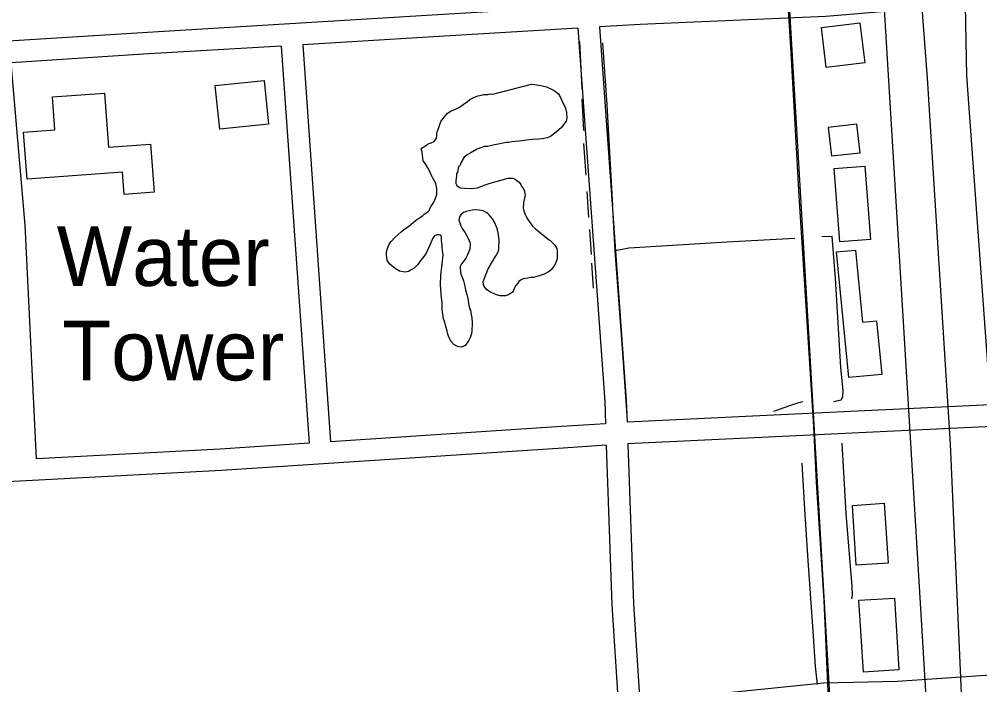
# Model space of a CAD drawing. Extents: x 3313447 to 3351316, y 703786 to 729172.
# Drawn here: x 3318120 to 3319454, y 712099 to 713023 of the extents above; entities that cross this region are included whole.
import ezdxf

# ---------------------------------------------------------------- set-up
doc = ezdxf.new("R2010")
doc.units = 0
for name, color, linetype in [('V-BLDG-OTLN', 7, 'Continuous'), ('V-DOMW-IDEN', 7, 'Continuous'), ('V-RAIL-TRAK', 7, 'Continuous'), ('V-ROAD-CNTR', 7, 'Continuous'), ('V-SITE-VEGE', 7, 'Continuous'), ('V-TOPO-SHOR', 7, 'Continuous')]:
    doc.layers.add(name, color=color, linetype=linetype)

msp = doc.modelspace()

# ---------------------------------------------------------------- linework, layer by layer
at = {"layer": 'V-BLDG-OTLN'}
for points in [[(3319294.4, 712962.4), (3319241, 712955.9), (3319234.3, 713011.4), (3319287.6, 713017.9)], [(3318466.4, 712877.4), (3318398.6, 712870.2), (3318392.2, 712930.9), (3318460, 712938.1)], [(3318238.2, 712920.5), (3318243.8, 712845.3), (3318302.2, 712849.7), (3318307.2, 712782.7), (3318265.5, 712779.6), (3318263.2, 712810.8), (3318130.8, 712800.9), (3318125.9, 712866), (3318169.4, 712869.3), (3318166, 712915.2)], [(3319243.7, 712872.8), (3319248.1, 712833.1), (3319287.9, 712837.5), (3319283.4, 712877.3)], [(3319259.7, 712713.7), (3319251.8, 712815.9), (3319294.4, 712819.2), (3319302.3, 712717)], [(3319272.3, 712525.4), (3319255, 712699.8), (3319281.4, 712702.4), (3319291.3, 712602.3), (3319310.7, 712604.2), (3319318, 712529.9)], [(3319282.5, 712264.7), (3319277.2, 712348), (3319321.6, 712350.8), (3319326.8, 712267.5)], [(3319292.5, 712116.5), (3319286.3, 712216.1), (3319335.7, 712219.1), (3319341.8, 712119.5)]]:
    msp.add_lwpolyline(points, close=True, dxfattribs=at)
at = {"layer": 'V-RAIL-TRAK'}
msp.add_lwpolyline([(3319315.7, 710879.4), (3319300.1, 711156.1), (3319292.5, 711279.1), (3319285.9, 711372.1), (3319282.6, 711439.6), (3319268.7, 711653.2), (3319259.6, 711840.3), (3319247.4, 712032.7), (3319244, 712078.9), (3319238.2, 712215.7), (3319227.6, 712380.3), (3319223.6, 712457.3), (3319217.1, 712559.1), (3319203.4, 712778), (3319192.1, 712976.4), (3319188.4, 713035.8), (3319181.3, 713174.6), (3319176.1, 713259.2)], dxfattribs=at)
at = {"layer": 'V-ROAD-CNTR'}
for points in [[(3319200.9, 715645.2), (3319216.7, 715284.7), (3319244.5, 714946.5), (3319270.4, 714529.8), (3319298.1, 714304.8), (3319315.2, 714045.1), (3319323.1, 713889.3), (3319368.3, 713112.6), (3319381.2, 712941.1), (3319413.2, 712432.8), (3319431.1, 712024.6), (3319452.3, 711724), (3319471.1, 711433.8), (3319475.9, 711305), (3319509.5, 710784.1), (3319530, 710456), (3319546.3, 710208.9), (3319558.3, 710026.2), (3319565.2, 709880.1), (3319575.7, 709725.1), (3319582.8, 709519.2), (3319592.9, 709284.4), (3319593.2, 709171.8)], [(3319104.4, 715556.2), (3319111.5, 715008.4), (3319106.8, 714793.8), (3319105.8, 714648.8), (3319107, 714540.6), (3319110.5, 714455.5), (3319112.5, 714365.8), (3319118.8, 714268.3), (3319122.2, 714163), (3319142.5, 713833.7), (3319173.1, 713319.1), (3319221.1, 712508.6), (3319264.3, 711756.9), (3319290.9, 711312.7), (3319362, 710097.5), (3319402.6, 709403.5), (3319416.2, 709171.5)], [(3319345.1, 714514.6), (3319371.4, 714068), (3319378, 713881.8), (3319405.6, 713508.6), (3319432.4, 713115.5), (3319435.8, 712944.4), (3319467.3, 712512), (3319484.1, 712134.4), (3319486.5, 712036.3), (3319512.8, 711766.8), (3319527.8, 711448.5), (3319527.4, 711327.4), (3319550.9, 711036.9), (3319567.8, 710785.7), (3319575.8, 710627.4), (3319594.4, 710397.1), (3319599, 710295), (3319616.4, 710052.6), (3319624.9, 709858.9), (3319631.7, 709695.3), (3319643.5, 709583.2), (3319653.2, 709388.3), (3319647.9, 709299.2), (3319653.3, 709171.9)], [(3319262.7, 713989.1), (3319296.4, 713448.2), (3319348.8, 712587.6), (3319394.3, 711836.6), (3319442.6, 710977.5), (3319493.5, 710218.9), (3319507.2, 709986.1)], [(3319720.9, 713095.9), (3319670, 713093.2), (3319238.6, 713056.7), (3318980.9, 713045.9), (3318693.7, 713028.5), (3318290.7, 713004.2), (3318030.2, 712987.7)], [(3319722.8, 713066), (3319672.1, 713063.3), (3319240.5, 713026.8), (3318982.4, 713015.9), (3318925.8, 713012.5)], [(3318895.9, 713010.7), (3318695.5, 712998.6), (3318514, 712987.6)], [(3318895.9, 713010.7), (3318933.2, 712492.1), (3318934.3, 712461.4)], [(3318925.8, 713012.5), (3318963.2, 712493.7), (3318964.2, 712463.5)], [(3318484, 712985.8), (3318292.5, 712974.3), (3318108.7, 712962.6)], [(3318484, 712985.8), (3318522.6, 712434.3)], [(3318514, 712987.6), (3318552.5, 712436.2)], [(3318143.9, 712412.7), (3318128.3, 712737.2), (3318108.7, 712962.6)], [(3319517.6, 712489.9), (3318964.2, 712463.5)], [(3318934.3, 712461.4), (3318873.4, 712457.3), (3318552.5, 712436.2)], [(3319520.3, 712460), (3318965.3, 712433.5)], [(3318935.3, 712431.4), (3318875.4, 712427.3), (3318400.7, 712396.2), (3317971.8, 712373.6), (3317590.7, 712351.4)], [(3318522.6, 712434.3), (3318399, 712426.2), (3318143.9, 712412.7)], [(3318935.3, 712431.4), (3318943, 712209.8), (3318952.1, 712073.7)], [(3318965.3, 712433.5), (3318973, 712211.3), (3318982.1, 712075.2)], [(3319773, 712128.3), (3319756.4, 712127.2), (3319543.9, 712117.2), (3319340, 712103.2), (3319236.9, 712101), (3318982.1, 712075.2)]]:
    msp.add_lwpolyline(points, dxfattribs=at)
at = {"layer": 'V-SITE-VEGE'}
for points in [[(3318693, 712715.9), (3318690.4, 712709.1), (3318685.4, 712698.4), (3318681.9, 712693.5), (3318676.3, 712686.5), (3318673.5, 712682.6), (3318668.7, 712677.5), (3318665.3, 712675.3), (3318660.5, 712672.9), (3318655.9, 712672), (3318648.3, 712673.3), (3318642.5, 712676.2), (3318634.8, 712682.8), (3318631, 712688.2), (3318630, 712695.9), (3318630.2, 712700.2), (3318631.7, 712704.8), (3318633.9, 712710.6), (3318636.7, 712714.5), (3318642.2, 712720.2), (3318650.5, 712727.8), (3318654.2, 712731), (3318660.7, 712735.4), (3318670.6, 712743.6), (3318677.1, 712748.3), (3318680.5, 712750.5), (3318682.2, 712752.4), (3318687.3, 712755.5), (3318689.7, 712758.1), (3318690.4, 712760), (3318692.2, 712763.3), (3318695.7, 712769.1), (3318697.2, 712772.3), (3318699, 712776.9), (3318699.8, 712780.2), (3318700.1, 712787.8), (3318699.3, 712792.4), (3318698.4, 712794.8), (3318694.1, 712803.2), (3318692.9, 712805.2), (3318689.5, 712813.3), (3318687.7, 712816.7), (3318684.3, 712822.1), (3318681.1, 712826.2), (3318679.6, 712838.2), (3318678.7, 712841.5), (3318678.8, 712843.8), (3318684.3, 712847.3), (3318686.6, 712849.2), (3318689.3, 712850.4), (3318692.3, 712851.3), (3318696.1, 712853.4), (3318699.6, 712857.9), (3318700, 712861.5), (3318700.2, 712865.8), (3318700.9, 712867.8), (3318702.1, 712871.4), (3318703.9, 712875.6), (3318705.8, 712881.2), (3318707.5, 712883.4), (3318710, 712887), (3318714.5, 712892.1), (3318718.9, 712895.5), (3318724.9, 712897.6), (3318731.7, 712901), (3318736.5, 712904.8), (3318738.5, 712906), (3318742.2, 712908.5), (3318745.7, 712911.4), (3318750.4, 712913.8), (3318757.1, 712916.5), (3318762.1, 712917.7), (3318765.5, 712918.5), (3318770.8, 712918.7), (3318774.1, 712919.2), (3318777.7, 712919), (3318831.5, 712932.8), (3318836.1, 712932.6), (3318844.7, 712931), (3318848, 712929.9), (3318852.2, 712929), (3318855.1, 712927.6), (3318859.4, 712926.1), (3318862.9, 712924), (3318868.4, 712920.1), (3318870.6, 712917.1), (3318873.4, 712911), (3318878.9, 712899.5), (3318880.3, 712893.5), (3318880.6, 712885.9), (3318879.8, 712881.6), (3318876.7, 712877.8), (3318873.2, 712872.9), (3318865.6, 712866), (3318857.8, 712860), (3318853.1, 712858.5), (3318846.4, 712856.8), (3318841.8, 712856.6), (3318832.8, 712856), (3318828.5, 712855.5), (3318824.8, 712855.3)], [(3318824.8, 712855.3), (3318814.5, 712853.7), (3318808.9, 712853.3), (3318804.2, 712852.8), (3318799.9, 712852), (3318796.3, 712851.8), (3318791.9, 712850.7), (3318787.6, 712849.8), (3318782.9, 712849), (3318780.3, 712848.8), (3318774.6, 712847.4), (3318770.6, 712846.5), (3318765.6, 712846.1), (3318761.2, 712844.6), (3318759.2, 712844), (3318755.2, 712842.2), (3318746.4, 712837.2), (3318743, 712835), (3318738.2, 712831.3), (3318733.3, 712823.5), (3318732.2, 712820.6), (3318730.8, 712818.3), (3318729.7, 712816), (3318729.2, 712813.1), (3318728.5, 712810.8), (3318727.4, 712808.5), (3318727.3, 712805.9), (3318726.3, 712798), (3318726.2, 712794.7), (3318727.8, 712792.3), (3318732.3, 712789.1), (3318738.9, 712788.6), (3318748.4, 712788.2), (3318756.4, 712788.9), (3318767.2, 712793.1), (3318774.2, 712795.4), (3318799.3, 712802.4), (3318805.6, 712802.2), (3318807.8, 712801.4), (3318814.3, 712796.8), (3318816.5, 712793.5), (3318817.7, 712791.1), (3318820.2, 712787.4), (3318821.7, 712784.3), (3318822.2, 712780.7), (3318822.8, 712778.6), (3318820.4, 712768.5), (3318820.1, 712760.6), (3318821, 712756.9), (3318822.8, 712751.9), (3318824, 712749.2), (3318826.5, 712744.8), (3318832.7, 712735.6), (3318836.9, 712731.8), (3318854.8, 712717.5), (3318856.8, 712716.1), (3318864.1, 712709.2), (3318866.6, 712704.8), (3318867.1, 712701.1), (3318867.2, 712694.5), (3318867, 712690.2), (3318864.8, 712684), (3318863, 712680.8), (3318859.5, 712675.6), (3318856.1, 712672.5), (3318849.3, 712669.1), (3318843.6, 712667), (3318834.2, 712664.4), (3318829.9, 712664.2), (3318826.2, 712663.4), (3318819.9, 712662.3), (3318817.2, 712661.1), (3318813.8, 712658.9), (3318812.4, 712656.6), (3318809.3, 712652.8), (3318807.9, 712650.2), (3318806.4, 712646.3)], [(3318806.4, 712646.3), (3318805.3, 712644), (3318799.5, 712640.3), (3318795.2, 712638.8), (3318787.9, 712639.1), (3318782.7, 712640.3), (3318774.5, 712643.9), (3318769.4, 712647.1), (3318765.9, 712651.9), (3318764.7, 712654.5), (3318764.2, 712658.9), (3318765.7, 712662.1), (3318767.5, 712667), (3318769, 712670.3), (3318771.5, 712676.4), (3318777.2, 712686.5), (3318779, 712690), (3318781.4, 712693.6), (3318785, 712700.1), (3318786.2, 712704.3), (3318786.7, 712716.9), (3318785, 712726.2), (3318783.6, 712732.5), (3318780, 712741), (3318777.5, 712745.7), (3318772.5, 712751.2), (3318770.9, 712753.2), (3318768.6, 712754.6), (3318764.4, 712756.8), (3318758.8, 712757.7), (3318754.2, 712758.5), (3318748.9, 712758.1), (3318740.9, 712756.1), (3318737.2, 712754.5), (3318733.4, 712751.4), (3318731.7, 712748.5), (3318730.5, 712744.6), (3318731.4, 712741.5), (3318733.5, 712736.2), (3318735.3, 712732.5), (3318739.4, 712726.3), (3318741.9, 712722.3), (3318743.7, 712718.6), (3318745.8, 712713.5), (3318746.1, 712710.5), (3318745.8, 712703.6), (3318742.1, 712694.8), (3318740.3, 712691.2), (3318736.8, 712686.1), (3318734.4, 712683.5), (3318732.3, 712679.6), (3318732.2, 712677), (3318733.2, 712669), (3318736.2, 712662.3), (3318737.1, 712659.9), (3318739.1, 712652.2), (3318739.9, 712647.2), (3318741.7, 712640.9), (3318742.8, 712637.2), (3318743.7, 712632.9), (3318743.8, 712628.2), (3318745.5, 712621.5), (3318746.8, 712618.9), (3318747.9, 712613.2), (3318748.7, 712608.5), (3318749.1, 712601.6), (3318748.6, 712589.3), (3318747.7, 712584.7), (3318746.6, 712581.8), (3318744.1, 712576.3), (3318739.2, 712569.9), (3318734.5, 712567.7), (3318731.2, 712567.9), (3318727.6, 712569), (3318723.7, 712571.5), (3318719.3, 712575.9), (3318716.2, 712582.7), (3318714.7, 712587), (3318714.2, 712590), (3318713.1, 712595), (3318710.7, 712603.4), (3318709.2, 712607.1), (3318707.4, 712620.1), (3318707.5, 712629.3), (3318706.7, 712636), (3318705.1, 712654.2), (3318705.7, 712668.1), (3318707.1, 712679.3), (3318707.7, 712686.9), (3318708.8, 712696.1), (3318708, 712701.4), (3318707.5, 712706.1), (3318707.3, 712709.7), (3318706.5, 712715.1), (3318706.7, 712720.7), (3318705.8, 712723), (3318703.2, 712723.8), (3318699.9, 712723.6), (3318696.9, 712722.4), (3318694.4, 712719.2), (3318693, 712715.9)]]:
    msp.add_lwpolyline(points, dxfattribs=at)
at = {"layer": 'V-TOPO-SHOR'}
for p, q in [((3318901.9, 712926.5), (3318898.6, 712992.3)), ((3318904.2, 712868.4), (3318901.8, 712912.7)), ((3318907.5, 712806.4), (3318904.4, 712850.3)), ((3318911.2, 712747.9), (3318908.9, 712783.9)), ((3318914.7, 712696.5), (3318912.6, 712731)), ((3319249.3, 712721.3), (3319235, 712720.7)), ((3318917.6, 712649.6), (3318915.5, 712684.2))]:
    msp.add_line(p, q, dxfattribs=at)
for points in [[(3318944.3, 712763.7), (3318936.5, 712904), (3318930.8, 712990.3)], [(3318964.3, 712472.6), (3318957.4, 712572.9), (3318947.9, 712701.6), (3318944.9, 712751.5)], [(3319197.5, 712718.6), (3319103, 712713.4), (3318974.5, 712705.5), (3318966.9, 712704.9), (3318947.9, 712701.6)], [(3319251, 712492.1), (3319261.6, 712494.4), (3319264.2, 712498.6), (3319264.6, 712507.7), (3319261.4, 712539.4), (3319254, 712663.4), (3319249.3, 712721.3)], [(3319208.3, 712491.6), (3319201.1, 712490.1), (3319189.9, 712486.1), (3319167.5, 712478.4)], [(3319276.5, 712218.1), (3319277.4, 712222.9), (3319277, 712235.4), (3319268.7, 712336.6), (3319263.1, 712434.3)], [(3319229, 712099.3), (3319226.1, 712124.3), (3319222.7, 712173.2), (3319215.9, 712271.5), (3319211.2, 712342.9), (3319207.6, 712406.5)]]:
    msp.add_lwpolyline(points, dxfattribs=at)

# ---------------------------------------------------------------- texts
at = {"layer": 'V-DOMW-IDEN'}
for s, p in [('Water', (3318172, 712652.6)), ('Tower', (3318179.8, 712521.5))]:
    msp.add_text(s, height=83, dxfattribs=at).set_placement(p)

doc.saveas('drawing.dxf')
